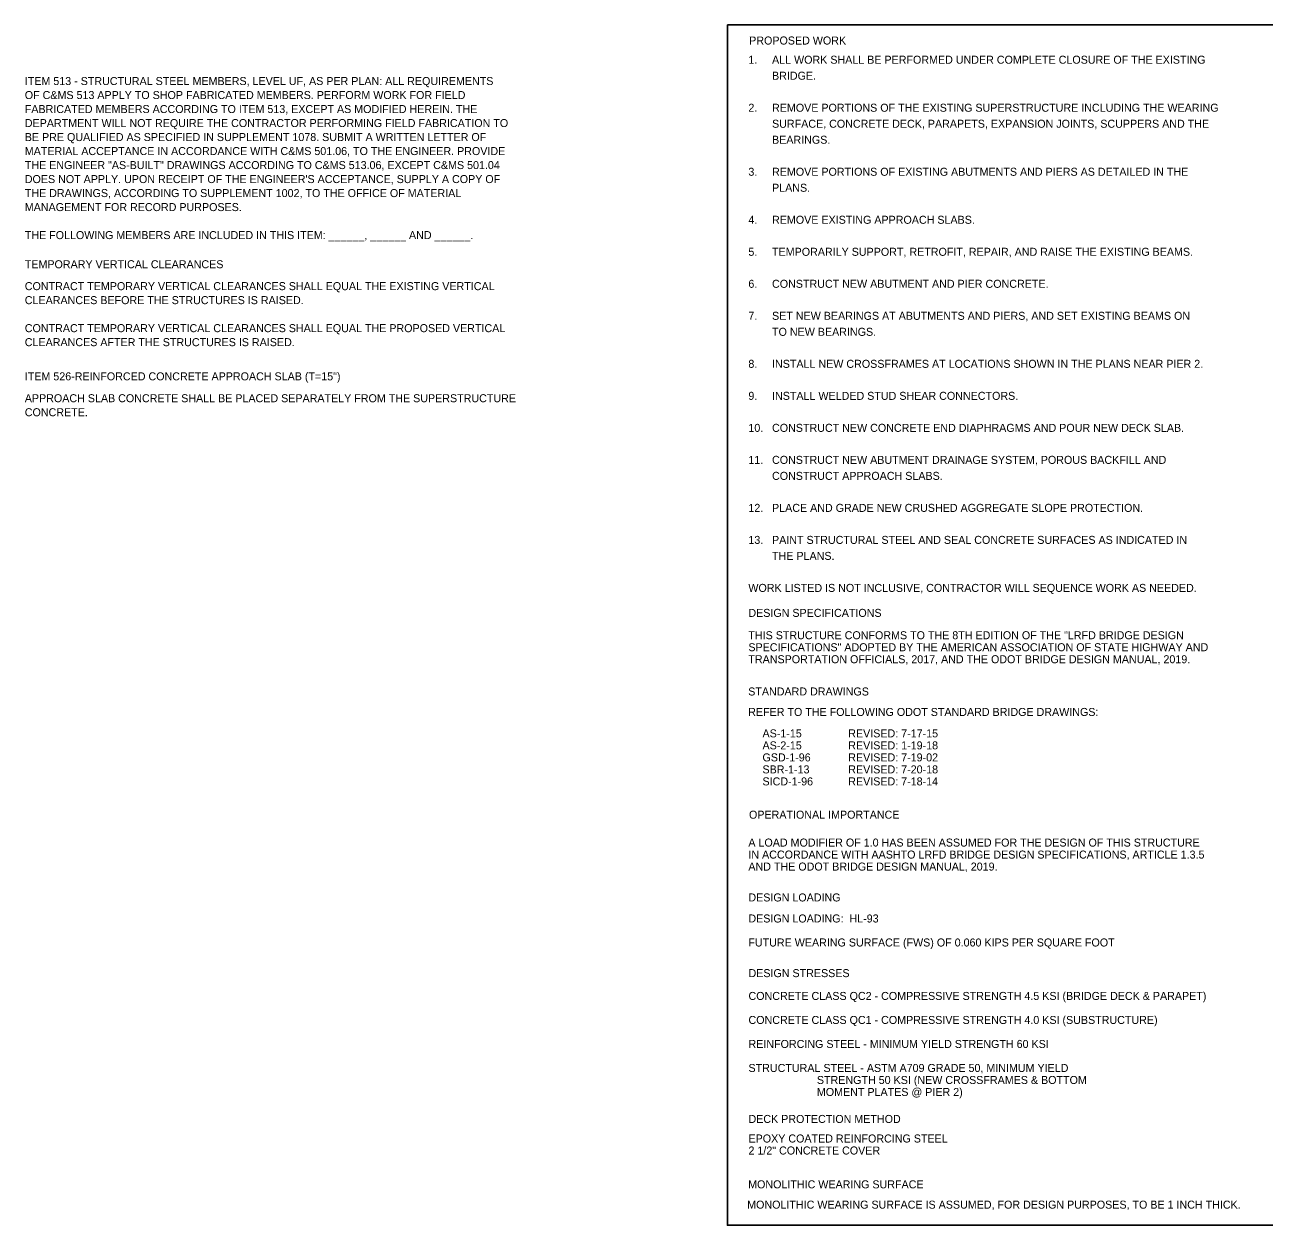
# Model space of a CAD drawing. Extents: x -10.6 to 33.4, y -28.4 to 21.5.
# Drawn here: x -10.29 to 11.39, y -28.43 to -7.43 of the extents above; entities that cross this region are included whole.
import ezdxf

# ---------------------------------------------------------------- set-up
doc = ezdxf.new("R2010")
doc.units = 0
doc.layers.add('BR_P_Gen_Text', color=7, linetype='Continuous')
doc.layers.add('SC_Scratch1', color=7, linetype='Continuous')

msp = doc.modelspace()

# ---------------------------------------------------------------- linework, layer by layer
at = {"layer": 'BR_P_Gen_Text'}
msp.add_line((2.382, -7.632), (2.382, -7.632), dxfattribs=at)
at = {"layer": 'SC_Scratch1'}
msp.add_lwpolyline([(2, -7.427), (32.5, -7.427), (32.5, -28.427), (2, -28.427)], close=True, dxfattribs=at)

# ---------------------------------------------------------------- texts
at = {"layer": 'BR_P_Gen_Text'}
for s, p in [('PROPOSED WORK', (2.382, -7.772)), ('1.', (2.368, -8.108)), ('ALL WORK SHALL BE PERFORMED UNDER COMPLETE CLOSURE OF THE EXISTING', (2.782, -8.108)), ('ITEM 513 - STRUCTURAL STEEL MEMBERS, LEVEL UF, AS PER PLAN: ALL REQUIREMENTS ', (-10.29, -8.481)), ('BRIDGE.', (2.782, -8.388)), ('OF C&MS 513 APPLY TO SHOP FABRICATED MEMBERS. PERFORM WORK FOR FIELD ', (-10.29, -8.726)), ('FABRICATED MEMBERS ACCORDING TO ITEM 513, EXCEPT AS MODIFIED HEREIN. THE ', (-10.29, -8.971)), ('2.', (2.368, -8.948)), ('REMOVE PORTIONS OF THE EXISTING SUPERSTRUCTURE INCLUDING THE WEARING', (2.782, -8.948)), ('DEPARTMENT WILL NOT REQUIRE THE CONTRACTOR PERFORMING FIELD FABRICATION TO ', (-10.29, -9.216)), ('SURFACE, CONCRETE DECK, PARAPETS, EXPANSION JOINTS, SCUPPERS AND THE', (2.782, -9.228)), ('BE PRE QUALIFIED AS SPECIFIED IN SUPPLEMENT 1078. SUBMIT A WRITTEN LETTER OF ', (-10.29, -9.461)), ('BEARINGS.', (2.782, -9.508)), ('MATERIAL ACCEPTANCE IN ACCORDANCE WITH C&MS 501.06, TO THE ENGINEER. PROVIDE ', (-10.29, -9.706)), ('THE ENGINEER "AS-BUILT" DRAWINGS ACCORDING TO C&MS 513.06, EXCEPT C&MS 501.04 ', (-10.29, -9.951)), ('3.', (2.368, -10.068)), ('REMOVE PORTIONS OF EXISTING ABUTMENTS AND PIERS AS DETAILED IN THE', (2.782, -10.068)), ("DOES NOT APPLY. UPON RECEIPT OF THE ENGINEER'S ACCEPTANCE, SUPPLY A COPY OF ", (-10.29, -10.196)), ('THE DRAWINGS, ACCORDING TO SUPPLEMENT 1002, TO THE OFFICE OF MATERIAL ', (-10.29, -10.441)), ('PLANS.  ', (2.782, -10.348)), ('MANAGEMENT FOR RECORD PURPOSES.', (-10.29, -10.686)), ('4.', (2.368, -10.908)), ('REMOVE EXISTING APPROACH SLABS.', (2.782, -10.908)), ('THE FOLLOWING MEMBERS ARE INCLUDED IN THIS ITEM: ______, ______ AND ______.', (-10.29, -11.176)), ('5.', (2.368, -11.468)), ('TEMPORARILY SUPPORT, RETROFIT, REPAIR, AND RAISE THE EXISTING BEAMS.', (2.782, -11.468)), ('TEMPORARY VERTICAL CLEARANCES', (-10.29, -11.686)), ('6.', (2.368, -12.028)), ('CONSTRUCT NEW ABUTMENT AND PIER CONCRETE.', (2.782, -12.028)), ('CONTRACT TEMPORARY VERTICAL CLEARANCES SHALL EQUAL THE EXISTING VERTICAL ', (-10.29, -12.069)), ('CLEARANCES BEFORE THE STRUCTURES IS RAISED. ', (-10.29, -12.314)), ('7.', (2.368, -12.588)), ('SET NEW BEARINGS AT ABUTMENTS AND PIERS, AND SET EXISTING BEAMS ON', (2.782, -12.588)), ('CONTRACT TEMPORARY VERTICAL CLEARANCES SHALL EQUAL THE PROPOSED VERTICAL ', (-10.29, -12.804)), ('TO NEW BEARINGS.', (2.782, -12.868)), ('CLEARANCES AFTER THE STRUCTURES IS RAISED.', (-10.29, -13.049)), ('8.', (2.368, -13.428)), ('INSTALL NEW CROSSFRAMES AT LOCATIONS SHOWN IN THE PLANS NEAR PIER 2.', (2.782, -13.428)), ('ITEM 526-REINFORCED CONCRETE APPROACH SLAB (T=15")', (-10.29, -13.647)), ('9.', (2.368, -13.988)), ('INSTALL WELDED STUD SHEAR CONNECTORS.', (2.782, -13.988)), ('APPROACH SLAB CONCRETE SHALL BE PLACED SEPARATELY FROM THE SUPERSTRUCTURE ', (-10.29, -14.03)), ('CONCRETE.', (-10.29, -14.275)), ('10.', (2.368, -14.548)), ('CONSTRUCT NEW CONCRETE END DIAPHRAGMS AND POUR NEW DECK SLAB.', (2.782, -14.548)), ('11.', (2.368, -15.108)), ('CONSTRUCT NEW ABUTMENT DRAINAGE SYSTEM, POROUS BACKFILL AND ', (2.782, -15.108)), ('CONSTRUCT APPROACH SLABS.', (2.782, -15.388)), ('12.', (2.368, -15.948)), ('PLACE AND GRADE NEW CRUSHED AGGREGATE SLOPE PROTECTION.', (2.782, -15.948)), ('13.', (2.368, -16.508)), ('PAINT STRUCTURAL STEEL AND SEAL CONCRETE SURFACES AS INDICATED IN ', (2.782, -16.508)), ('THE PLANS.', (2.782, -16.788)), ('WORK LISTED IS NOT INCLUSIVE, CONTRACTOR WILL SEQUENCE WORK AS NEEDED.', (2.368, -17.348)), ('DESIGN SPECIFICATIONS', (2.368, -17.785)), ('THIS STRUCTURE CONFORMS TO THE 8TH EDITION OF THE "LRFD BRIDGE DESIGN', (2.368, -18.176)), ('SPECIFICATIONS" ADOPTED BY THE AMERICAN ASSOCIATION OF STATE HIGHWAY AND', (2.368, -18.386)), ('TRANSPORTATION OFFICIALS, 2017, AND THE ODOT BRIDGE DESIGN MANUAL, 2019.', (2.368, -18.596)), ('STANDARD DRAWINGS ', (2.365, -19.16)), ('REFER TO THE FOLLOWING ODOT STANDARD BRIDGE DRAWINGS:', (2.365, -19.518)), ('AS-1-15', (2.615, -19.893)), ('REVISED: 7-17-15', (4.115, -19.893)), ('AS-2-15', (2.615, -20.103)), ('REVISED: 1-19-18', (4.115, -20.103)), ('GSD-1-96', (2.615, -20.313)), ('REVISED: 7-19-02', (4.115, -20.313)), ('SBR-1-13', (2.615, -20.523)), ('SICD-1-96', (2.615, -20.733)), ('REVISED: 7-20-18', (4.115, -20.523)), ('REVISED: 7-18-14', (4.115, -20.733)), ('OPERATIONAL IMPORTANCE', (2.379, -21.315)), ('A LOAD MODIFIER OF 1.0 HAS BEEN ASSUMED FOR THE DESIGN OF THIS STRUCTURE', (2.368, -21.803)), ('IN ACCORDANCE WITH AASHTO LRFD BRIDGE DESIGN SPECIFICATIONS, ARTICLE 1.3.5', (2.368, -22.013)), ('AND THE ODOT BRIDGE DESIGN MANUAL, 2019.', (2.368, -22.223)), ('DESIGN LOADING', (2.368, -22.763)), ('DESIGN LOADING:  HL-93 ', (2.368, -23.131)), ('FUTURE WEARING SURFACE (FWS) OF 0.060 KIPS PER SQUARE FOOT ', (2.368, -23.551)), ('DESIGN STRESSES', (2.37, -24.087)), ('CONCRETE CLASS QC2 - COMPRESSIVE STRENGTH 4.5 KSI (BRIDGE DECK & PARAPET)', (2.37, -24.486)), ('CONCRETE CLASS QC1 - COMPRESSIVE STRENGTH 4.0 KSI (SUBSTRUCTURE)', (2.37, -24.906)), ('REINFORCING STEEL - MINIMUM YIELD STRENGTH 60 KSI  ', (2.37, -25.326)), ('STRUCTURAL STEEL - ASTM A709 GRADE 50, MINIMUM YIELD', (2.37, -25.746)), ('                       STRENGTH 50 KSI (NEW CROSSFRAMES & BOTTOM', (2.37, -25.956)), ('                       MOMENT PLATES @ PIER 2)', (2.37, -26.166)), ('DECK PROTECTION METHOD', (2.37, -26.638)), ('EPOXY COATED REINFORCING STEEL', (2.37, -26.98)), ('2 1/2" CONCRETE COVER', (2.37, -27.19)), ('MONOLITHIC WEARING SURFACE', (2.364, -27.782)), ('MONOLITHIC WEARING SURFACE IS ASSUMED, FOR DESIGN PURPOSES, TO BE 1 INCH THICK.', (2.347, -28.137))]:
    msp.add_text(s, height=0.14, dxfattribs=at).set_placement(p)

doc.saveas('drawing.dxf')
